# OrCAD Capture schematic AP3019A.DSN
size Custom; title: AP3019A, 4WHITE LED STEP-UP CONVERTER; rev: 1.0; note: DS41298 Rev. 3 - 2
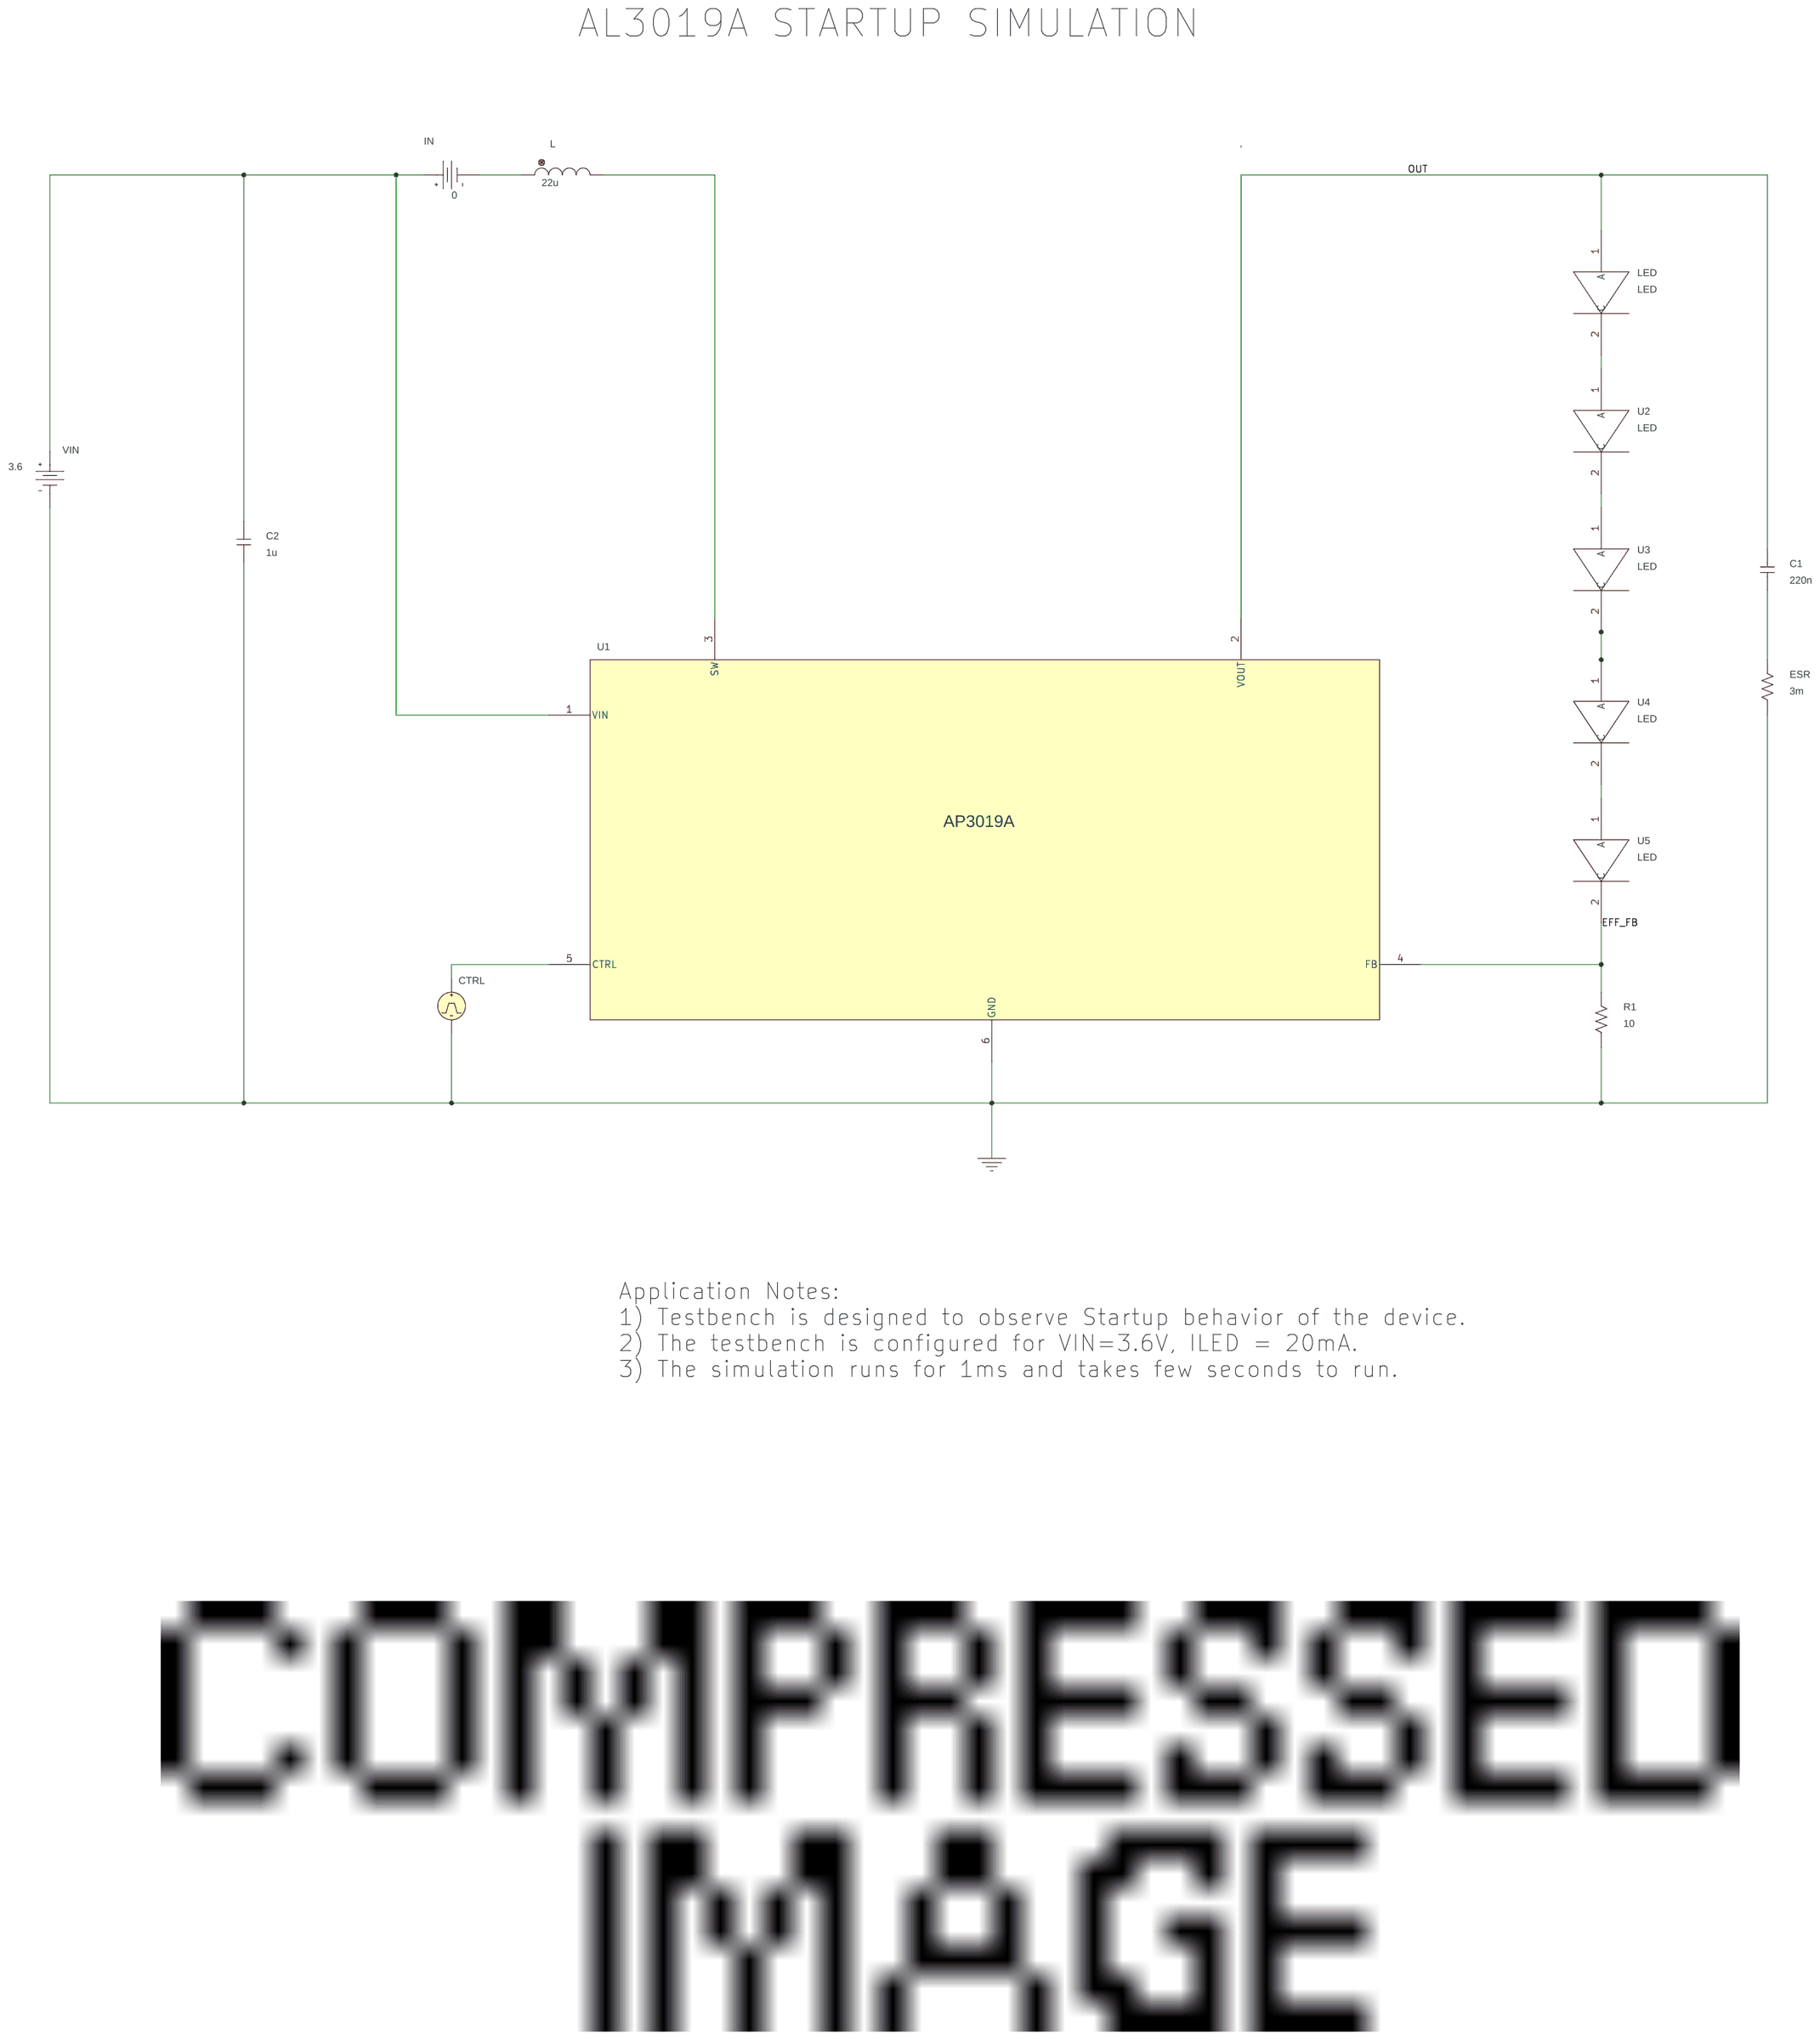
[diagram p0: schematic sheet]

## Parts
C1  220n  [RAD/CK05]
C2  1u  [RAD/CK05]
CTRL  VPULSE
ESR  3m  [AX/RC05]
IN  VDC
L  22u  [DISC/.350x.175/LS.200x.100/.034]
LED  LED
R1  10  [AX/RC05]
U1  AP3019A
U2  LED
U3  LED
U4  LED
U5  LED
VIN  VDC

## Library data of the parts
C1 = C
C2 = C: IC: 0
CTRL = VPULSE: AC: 0; AppProp: Pulse$Voltage$0$-1; DC: 0; PER: 1.0000e+9; PW: 1.0000e+9; TD: 100u; TF: 10n; TR: 10n; V1: 0; V2: 3.6
ESR R1 = R
IN = VDC: DC: 0
L = L
LED U2-U5 = LED_0
U1 = AP3019A_2
VIN = VDC: DC: 3.6

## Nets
0: C2.1 CTRL.2(-) ESR.1 R1.1 U1.6(GND) VIN.1(-)
EFF_FB: R1.2 U1.4(FB) U5.2(C)
OUT: C1.2 LED.1(A) U1.2(VOUT)
N35344: LED.2(C) U2.1(A)
N35350: U2.2(C) U3.1(A)
N35356: U4.2(C) U5.1(A)
N35460: U3.2(C) U4.1(A)
N35514: C1.1 ESR.2
N35704: CTRL.1(+) U1.5(CTRL)
N35718: C2.2 IN.0(+) U1.1(VIN) VIN.0(+)
N35732: IN.1(-) L.1
N36149: L.2 U1.3(SW)

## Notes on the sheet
- AL3019A STARTUP SIMULATION
- Application Notes:
  1) Testbench is designed to observe Startup behavior of the device.
  2) The testbench is configured for VIN=3.6V, ILED = 20mA.
  3) The simulation runs for 1ms and takes few seconds to run.
